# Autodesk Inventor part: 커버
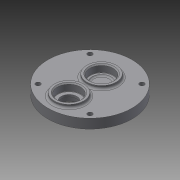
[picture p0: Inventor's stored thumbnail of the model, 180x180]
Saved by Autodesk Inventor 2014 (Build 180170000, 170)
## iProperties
Created: 2015-07
Part Number: 커버
Material: Generic
Document SubType Name: Modeling
Designer: Administrator
Density: 1 g/cm^3
Appearance: Default
Author: Administrator
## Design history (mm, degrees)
sketch "스케치1"
  geometry: C1 r 40 at (0, 0); 1 further point
  constraints: 1 centre point, 1 coincident
  dimensions: "d0" = 80 diameter of C1
extrude "돌출1" new body sketch "스케치1" distance "d1" = 9; taper "d2" = 0 deg
sketch "스케치2"
  geometry: C1 r 40 at (0, 0) reference; C2 r 15 at (0, -20)
  constraints: 1 centre point, 1 vertical alignment
  dimensions: "d3" = 30 diameter of C2; "d4" = 20 distance of C2.centre C1.centre
extrude "돌출2" join sketch "스케치2" distance "d5" = 4; taper "d6" = 0 deg
sketch "스케치3"
  geometry: C1 r 15 at (0, 0) reference; C2 r 11 at (0, 0); 1 further point
  constraints: 1 centre point, 1 coincident
  dimensions: "d7" = 22 diameter of C2
extrude "돌출3" cut sketch "스케치3" distance "d8" = 7; taper "d9" = 0 deg
sketch "스케치4"
  geometry: C1 r 11 at (0, 0) reference; C2 r 7.5 at (0, 0); 1 further point
  constraints: 1 centre point, 1 coincident
  dimensions: "d10" = 15 diameter of C2
extrude "돌출4" cut sketch "스케치4" distance "d11" = 2; taper "d12" = 0 deg
sketch "스케치5"
  geometry: C1 r 40 at (0, 0) reference; C2 r 14 at (0, -20)
  constraints: 1 centre point, 1 vertical alignment
  dimensions: "d13" = 28 diameter of C2; "d14" = 20 distance of C2.centre C1.centre
extrude "돌출5" join sketch "스케치5" distance "d15" = 3; taper "d16" = 0 deg
sketch "스케치6"
  geometry: C1 r 14 at (0, 0) reference; C2 r 11 at (0, 0); 1 further point
  constraints: 1 centre point, 1 coincident
  dimensions: "d17" = 22 diameter of C2
extrude "돌출6" cut sketch "스케치6" distance "d18" = 7; taper "d19" = 0 deg
sketch "스케치7"
  geometry: C1 r 40 at (0, 0) reference; C2 r 14 at (0, 11)
  constraints: 1 centre point, 1 vertical alignment
  dimensions: "d20" = 28 diameter of C2; "d21" = 11 distance of C2.centre C1.centre
extrude "돌출7" join sketch "스케치7" distance "d22" = 3; taper "d23" = 0 deg
sketch "스케치8"
  geometry: C1 r 14 at (0, 0) reference; C2 r 11 at (0, 0); 1 further point
  constraints: 1 centre point, 1 coincident
  dimensions: "d24" = 22 diameter of C2
extrude "돌출8" cut sketch "스케치8" distance "d25" = 7; taper "d26" = 0 deg
sketch "스케치9"
  geometry: C1 r 9 at (0, 0); 2 further points
  constraints: 1 centre point, 1 coincident, 1 vertical alignment
  dimensions: "d27" = 18 diameter of C1
extrude "돌출9" cut sketch "스케치9" distance "d28" = 1; taper "d29" = 0 deg
chamfer "모따기1" distance "d30" = 1; stored, may be unused: second distance "d31" = 2, angle "d32" = 45 deg
chamfer "모따기2" distance "d33" = 1; stored, may be unused: second distance "d34" = 2, angle "d35" = 45 deg
fillet "모깎기1" dims "d36" = 0.3
fillet "모깎기2" dims "d37" = 2
fillet "모깎기3" dims "d38" = 2
sketch "스케치10"
  geometry: L1 (0, 0)-(0, 35); L2 (0, 0)-(-24.749, 24.749); C1 r 40 at (0, 0) reference; C2 r 2.25 at (-24.749, 24.749); A1 r 35 centre (0, 0) between (0, 35) and (-24.749, 24.749)
  constraints: 4 end point, 2 centre point, 2 coincident, 2 point on circle, 1 vertical
  dimensions: "d39" = 70 diameter of A1; "d40" = 45 deg angle of L1 L2; "d41" = 4.5 diameter of C2
extrude "돌출10" cut sketch "스케치10" distance "d42" = 4.6; taper "d43" = 0 deg
sketch "스케치11"
  geometry: C1 r 2.25 at (0, 0) reference; C2 r 4 at (0, 0); 1 further point
  constraints: 1 centre point, 1 coincident
  dimensions: "d44" = 8 diameter of C2
extrude "돌출11" cut sketch "스케치11" distance "d45" = 4.4; taper "d46" = 0 deg
fillet "모깎기4" dims "d47" = 2
sketch "스케치12"
  geometry: 1 further point
node "솔리드1"
mirror "대칭1"
mirror "대칭2"
